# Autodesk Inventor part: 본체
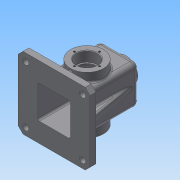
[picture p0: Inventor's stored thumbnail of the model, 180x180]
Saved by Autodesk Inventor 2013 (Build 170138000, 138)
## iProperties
Created: 2018-10
Part Number: 본체
Material: 일반
Document SubType Name: Modeling
Designer: Administrator
Density: 1 g/cm^3
Author: Administrator
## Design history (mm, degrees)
sketch "스케치1"
  geometry: L1 (-32.5, -32.5)-(32.5, -32.5); L2 (32.5, -32.5)-(32.5, 32.5); L3 (32.5, 32.5)-(-32.5, 32.5); L4 (-32.5, 32.5)-(-32.5, -32.5); L5 (-32.5, -32.5)-(32.5, 32.5); L6 (32.5, -32.5)-(-32.5, 32.5); 1 further point
  constraints: 12 end point, 2 midpoint, 2 parallel, 1 horizontal, 1 perpendicular
  dimensions: "d0" = 65 distance of L3.end L2.end; "d1" = 65 distance of L2.end L1.end
extrude "돌출1" new body sketch "스케치1" stored distance "d2" = 110; taper "d3" = 0 deg
sketch "스케치2"
  geometry: L1 (-27.5, -27.5)-(27.5, -27.5); L2 (27.5, -27.5)-(27.5, 27.5); L3 (27.5, 27.5)-(-27.5, 27.5); L4 (-27.5, 27.5)-(-27.5, -27.5); L5 (-27.5, -27.5)-(27.5, 27.5); L6 (27.5, -27.5)-(-27.5, 27.5); 1 further point
  constraints: 12 end point, 2 midpoint, 2 parallel, 1 horizontal, 1 perpendicular
  dimensions: "d4" = 55 distance of L3.end L2.end; "d5" = 55 distance of L1.end L2.end
extrude "돌출2" cut sketch "스케치2" distance "d6" = 105; taper "d7" = 0 deg
node "작업 평면1"
sketch "스케치3"
  geometry: C1 r 20 at (0, 0); 1 further point
  constraints: 1 centre point, 1 coincident
  dimensions: "d9" = 40 diameter of C1
extrude "돌출3" join sketch "스케치3" stored distance "d10" = 105; taper "d11" = 7 deg
fillet "모깎기2" dims "d13" = 8
fillet "모깎기3" dims "d14" = 3
fillet "모깎기4" dims "d15" = 3
hole "구멍1" diameter "d18" = 22.835; stored, may be unused: countersink angle "d22" = 90 deg, drill point angle "d24" = 118 deg; dims "d16" = 10, "d17" = 10, "d19" = 6, "d20" = 4, "d21" = 2, "d23" = 8
sketch "스케치8"
  geometry: C1 r 27.5 at (32.5, 55); 1 further point
  constraints: 1 centre point, 1 coincident
  dimensions: "d45" = 55 diameter of C1
extrude "돌출7" join sketch "스케치8" distance "d46" = 15; taper "d47" = 0 deg
hole "구멍4" diameter "d59" = 30; stored, may be unused: countersink angle "d63" = 90 deg, drill point angle "d65" = 0 deg; dims "d57" = 10, "d58" = 10, "d60" = 8, "d61" = 35, "d62" = 17, "d64" = 20
sketch "스케치9"
  geometry: C1 r 17.5 at (0, 0) reference; 1 further point
  constraints: 1 vertical alignment
  dimensions: "d66" = 21 distance of C1.centre point (0, 21)
hole "구멍5" sketch "스케치9" at (0, 21) diameter "d67" = 3.242; stored, may be unused: countersink angle "d71" = 90 deg, drill point angle "d73" = 118 deg; dims "d68" = 8, "d69" = 35, "d70" = 17, "d72" = 10
sketch "스케치10"
  geometry: L1 (32.5, -32.5)-(32.5, 32.5) reference; L2 (32.5, 32.5)-(-32.5, 32.5) reference; L3 (-32.5, 32.5)-(-32.5, -32.5) reference; L4 (-32.5, -32.5)-(32.5, -32.5) reference; L5 (-60, -60)-(60, -60); L6 (60, -60)-(60, 60); L7 (60, 60)-(-60, 60); L8 (-60, 60)-(-60, -60); L9 (-60, -60)-(60, 60); L10 (60, -60)-(-60, 60); 1 further point
  constraints: 12 end point, 2 midpoint, 2 parallel, 1 horizontal, 1 perpendicular
  dimensions: "d77" = 120 distance of L7.end L6.end; "d78" = 120 distance of L6.end L5.end
extrude "돌출8" join sketch "스케치10" distance "d79" = 10; taper "d80" = 0 deg
chamfer "모따기1" distance "d81" = 8; stored, may be unused: second distance "d82" = 2, angle "d83" = 45 deg
sketch "스케치12"
  geometry: L1 (44.625, -25.86)-(48, -45); L2 (52, -45)-(60, -45) reference; L3 (52, -45)-(-52, -45) reference; L4 (24.5, 50)-(11.418, 50) reference; L5 (11.418, 50)-(11.418, 65) reference; L6 (11.418, 65)-(20, 65) reference; L7 (20, 65)-(21.228, 55) reference; L8 (21.228, 55)-(24.5, 55) reference; L9 (32.5, 47)-(32.5, -45) reference; L10 (32.5, -45)-(60, -45) reference; L11 (60, -45)-(60, -55) reference; L12 (60, -55)-(27.5, -55) reference; L13 (27.5, -55)-(27.5, 47) reference; L14 (-24.5, 55)-(-21.228, 55) reference; L15 (-21.228, 55)-(-20, 65) reference; L16 (-20, 65)-(-11.418, 65) reference; L17 (-11.418, 65)-(-11.418, 50) reference; L18 (-11.418, 50)-(-24.5, 50) reference; L19 (-27.5, 47)-(-27.5, -55) reference; L20 (-27.5, -55)-(-60, -55) reference; L21 (-60, -55)-(-60, -45) reference; L22 (-60, -45)-(-32.5, -45) reference; L23 (-32.5, -45)-(-32.5, 47) reference; A1 r 3 centre (24.5, 47) between (27.5, 47) and (24.5, 50) reference; A2 r 8 centre (24.5, 47) between (32.5, 47) and (24.5, 55) reference; A3 r 8 centre (-24.5, 47) between (-24.5, 55) and (-32.5, 47) reference; A4 r 3 centre (-24.5, 47) between (-24.5, 50) and (-27.5, 47) reference; 1 further point
  constraints: 2 end point, 1 point on line
  dimensions: "d89" = 12 horizontal distance of L11.end L1.end; "d90" = 10 deg angle of L11 L1
feature "리브1" sketch "스케치12" dims "d91" = 1, "d92" = 10, "d93" = 0, "d94" = 0, "d95" = 1, "d96" = 1
sketch "스케치13"
  geometry: L1 (-35.906, 42.5)-(-41.908, 42.5); L2 (-17.5, 30.5)-(-15, 30.5) reference; L3 (-15, 30.5)-(-15, 27.5) reference; L4 (-15, 27.5)-(-55, 27.5) reference; L5 (-55, 27.5)-(-55, 60) reference; L6 (-55, 60)-(-45, 60) reference; L7 (-45, 60)-(-45, 32.5) reference; L8 (-45, 32.5)-(-27.5, 32.5) reference; L9 (-27.5, 32.5)-(-27.5, 47.5) reference; L10 (-27.5, 47.5)-(-22.621, 47.5) reference; L11 (-22.621, 47.5)-(-22.621, 37.5) reference; L12 (-22.621, 37.5)-(-21, 36.526) reference; L13 (-21, 36.526)-(-19.379, 37.5) reference; L14 (-19.379, 37.5)-(-19.379, 47.5) reference; L15 (-19.379, 47.5)-(-17.5, 47.5) reference; L16 (-17.5, 47.5)-(-17.5, 30.5) reference; L17 (47, 27.5)-(15, 27.5) reference; L18 (15, 27.5)-(15, 30.5) reference; L19 (15, 30.5)-(17.5, 30.5) reference; L20 (17.5, 30.5)-(17.5, 47.5) reference; L21 (17.5, 47.5)-(19.379, 47.5) reference; L22 (19.379, 47.5)-(19.379, 37.5) reference; L23 (19.379, 37.5)-(21, 36.526) reference; L24 (21, 36.526)-(22.621, 37.5) reference; L25 (22.621, 37.5)-(22.621, 47.5) reference; L26 (22.621, 47.5)-(27.5, 47.5) reference; L27 (27.5, 47.5)-(27.5, 32.5) reference; L28 (27.5, 32.5)-(47, 32.5) reference; L29 (55, 24.5)-(55, 21.228) reference; L30 (55, 21.228)-(65, 20) reference; L31 (65, 20)-(65, 11.418) reference; L32 (65, 11.418)-(50, 11.418) reference; L33 (50, 11.418)-(50, 24.5) reference; L34 (47, -32.5)-(-45, -32.5) reference; L35 (-45, -32.5)-(-45, -60) reference; L36 (-45, -60)-(-55, -60) reference; L37 (-55, -60)-(-55, -27.5) reference; L38 (-55, -27.5)-(47, -27.5) reference; L39 (50, -24.5)-(50, -11.418) reference; L40 (50, -11.418)-(65, -11.418) reference; L41 (65, -11.418)-(65, -20) reference; L42 (65, -20)-(55, -21.228) reference; L43 (55, -21.228)-(55, -24.5) reference; A1 r 3 centre (47, 24.5) between (50, 24.5) and (47, 27.5) reference; A2 r 8 centre (47, 24.5) between (55, 24.5) and (47, 32.5) reference; A3 r 8 centre (47, -24.5) between (47, -32.5) and (55, -24.5) reference; A4 r 3 centre (47, -24.5) between (47, -27.5) and (50, -24.5) reference; 1 further point
  constraints: 2 end point, 1 horizontal
  dimensions: "d97" = 15 distance between parallel lines of L4 L1
feature "리브2" sketch "스케치13" dims "d98" = 1, "d99" = 6, "d100" = 0, "d101" = 0, "d102" = 1, "d103" = 1
sketch "스케치14"
  geometry: 5 further points
  constraints: 2 horizontal alignment, 2 vertical alignment
  dimensions: "d105" = 95 distance of point (-47.5, -47.5) point (47.5, -47.5); "d107" = 95 distance of point (47.5, -47.5) point (47.5, 47.5); "d108" = 47.5 horizontal distance of point (0, 0) point (47.5, -47.5); "d109" = 47.5 horizontal distance of point (0, 0) point (-47.5, -47.5)
hole "구멍6" sketch "스케치14" at (-47.5, -47.5), (-47.5, 47.5), (47.5, 47.5), (47.5, -47.5) diameter "d110" = 10; stored, may be unused: countersink angle "d114" = 90 deg, drill point angle "d116" = 0 deg; dims "d111" = 8, "d112" = 35, "d113" = 17, "d115" = 10
sketch "스케치15"
  geometry: L1 (0, 0)-(0, -92) reference; L2 (12.5, 18)-(52.5, 18) reference; 1 further point
  constraints: 1 other
  dimensions: "d117" = 32.5 distance from line of L1 point (32.5, -8); "d118" = 26 distance from line of point (32.5, -8) L2
feature "엠보싱1" sketch "스케치15" dims "d0" = 65, "d1" = 65, "d119" = 0.5, "d120" = 0
fillet "모깎기7" dims "d121" = 8
fillet "모깎기8" dims "d122" = 3
fillet "모깎기9" dims "d123" = 3
fillet "모깎기10" dims "d124" = 3
fillet "모깎기11" dims "d125" = 1
fillet "모깎기12" dims "d126" = 0.3
chamfer "모따기2" distance "d127" = 1; stored, may be unused: second distance "d128" = 2, angle "d129" = 45 deg
fillet "모깎기13" dims "d130" = 3
node "솔리드1"
pattern_circular "원형 패턴2" dims angle "d75" = 360 deg
mirror "대칭2"
mirror "대칭3"
mirror "대칭4"
node "절단 모서리 투영1"
node "절단 모서리 투영2"
